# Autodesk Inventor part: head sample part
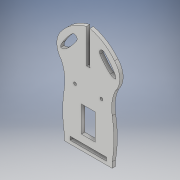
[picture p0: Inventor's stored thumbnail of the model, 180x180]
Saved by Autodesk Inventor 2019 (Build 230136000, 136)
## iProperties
Created: 2020-02
Part Number: head sample part
Material: Generic
Document SubType Name: Modeling
Designer: shivu
Density: 1 g/cm^3
Appearance: Default
Author: shivu
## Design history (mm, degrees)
sketch "Sketch1"
  geometry: L1 (0, 0)-(42, 0); L2 (0, 0)-(0, 5); L3 (42, 0)-(42, 5); L4 (21, 3)-(37, 3); L5 (37, 3)-(37, 6); L6 (37, 6)-(21, 6); L7 (5, 6)-(21, 6); L8 (5, 3)-(5, 6); L9 (21, 3)-(5, 3); L10 (21, 35.493)-(27, 35.493); L11 (27, 35.493)-(27, 12.493); L12 (27, 12.493)-(21, 12.493); L13 (21, 35.493)-(15, 35.493); L14 (15, 35.493)-(15, 12.493); L15 (15, 12.493)-(21, 12.493); L16 (19.5, 96.689)-(19.5, 66.689); L17 (22.5, 96.689)-(22.5, 66.689); L18 (19.5, 66.689)-(22.5, 66.689); C1 r 1.25 at (9.383, 48.038); C2 r 1.25 at (32.617, 48.038); A1 r 105.381 centre (103.918, 22.5) between (0, 40) and (0, 5); A2 r 105.381 centre (-61.918, 22.5) between (42, 5) and (42, 40); A3 r 34.616 centre (-34.136, 45.749) between (0, 40) and (-2.679, 60.197); A4 r 17.128 centre (10.493, 71.146) between (-2.062, 82.797) and (-2.679, 60.197); A5 r 39.729 centre (29.085, 58.134) between (19.5, 96.689) and (-2.062, 82.797); A6 r 34.616 centre (76.136, 45.749) between (44.679, 60.197) and (42, 40); A7 r 17.128 centre (31.507, 71.146) between (44.679, 60.197) and (44.062, 82.797); A8 r 39.729 centre (12.915, 58.134) between (44.062, 82.797) and (22.5, 96.689); A9 r 2.684 centre (8.539, 82.9) between (10.812, 81.474) and (7.395, 85.328); A10 r 6.009 centre (2.786, 69.997) between (-1.812, 73.865) and (-3.197, 69.44); A11 r 5.39 centre (-2.143, 74.726) between (-3.197, 69.44) and (1.709, 70.956); A12 r 2.684 centre (33.461, 82.9) between (34.605, 85.328) and (31.188, 81.474); A13 r 6.009 centre (39.214, 69.997) between (45.197, 69.44) and (43.812, 73.865); A14 r 5.39 centre (44.143, 74.726) between (40.291, 70.956) and (45.197, 69.44); 3 further points; 4 other entities
  constraints: 36 end point, 28 point on circle, 16 centre point, 4 horizontal, 3 vertical, 2 parallel, 2 perpendicular, 1 midpoint, 1 tangent, 16 other
extrude "Extrusion1" new body sketch "Sketch1" distance "d7" = 2; taper "d8" = 0 deg
sketch "Sketch2"
  geometry: L1 (0, 0)-(42, 0) reference; L2 (3.6, 3.586)-(3.6, 5.586); L3 (26.4, 3.586)-(26.4, 5.586); L4 (3.6, 5.586)-(26.4, 5.586)
  constraints: 6 end point, 2 vertical
  dimensions: "d38" = 2 distance of L2.start L2.end; "d39" = 2 distance of L3.start L3.end; "d46" = 22.8 distance of L2.end L3.end
extrude "Extrusion7" join sketch "Sketch1" distance "d58" = 3; taper "d59" = 0 deg
body "Solid1"
